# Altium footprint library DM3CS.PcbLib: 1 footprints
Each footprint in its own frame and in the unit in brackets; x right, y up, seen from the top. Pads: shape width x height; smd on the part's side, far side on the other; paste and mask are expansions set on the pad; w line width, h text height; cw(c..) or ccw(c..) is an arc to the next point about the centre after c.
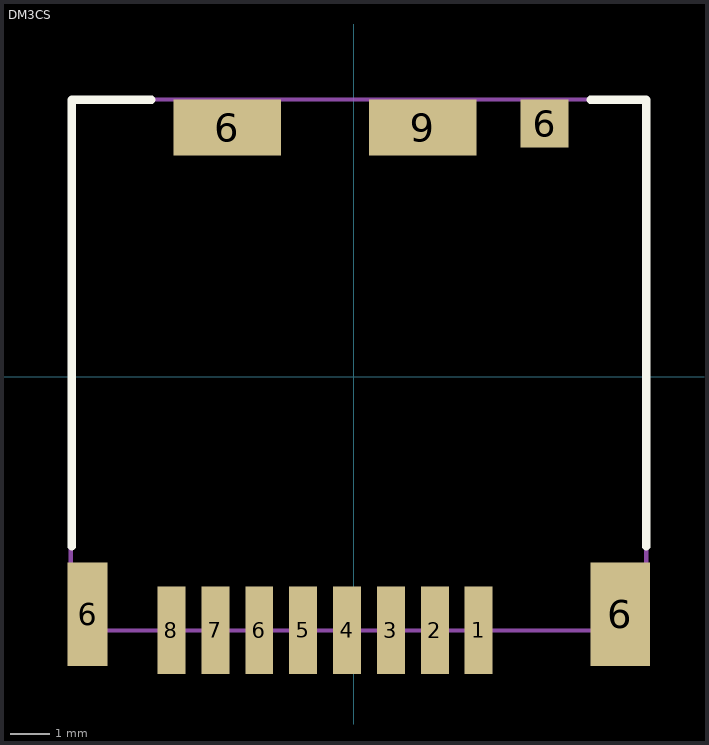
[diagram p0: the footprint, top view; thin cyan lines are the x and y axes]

## DM3CS [mm] "DM3CS Micro SD Card Holder"
pads (13):
  rect 0.7x2.2 smd: 1(3.125,-6.35) 2(2.025,-6.35) 3(0.925,-6.35) 4(-0.175,-6.35) 5(-1.275,-6.35) 6(-2.375,-6.35) 7(-3.475,-6.35) 8(-4.575,-6.35)
  rect 1x2.6 smd: 6(-6.675,-5.95)
  rect 2.7x1.4 smd: 6(-3.175,6.25) 9(1.725,6.25)
  rect 1.2x1.2 smd: 6(4.775,6.35)
  rect 1.5x2.6 smd: 6(6.675,-5.95)
Top Overlay:
  lines w0.203: -7.075,-4.25 -7.075,6.95 -5.075,6.95 ; 5.925,6.95 7.325,6.95 7.325,-4.25
Mechanical 31:
  lines w0.102: -7.1,-6.35 7.325,-6.35 7.325,6.95 -7.1,6.95 -7.1,-6.35
  text ".Comment" at -3.875,1.3 h0.76
  text ".Designator" at -3.9,3.025 h0.76
3D body "DM3CS-SF.stp": height 1.88, standoff -0.05, extent -6.8,-7.15 7,6.95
